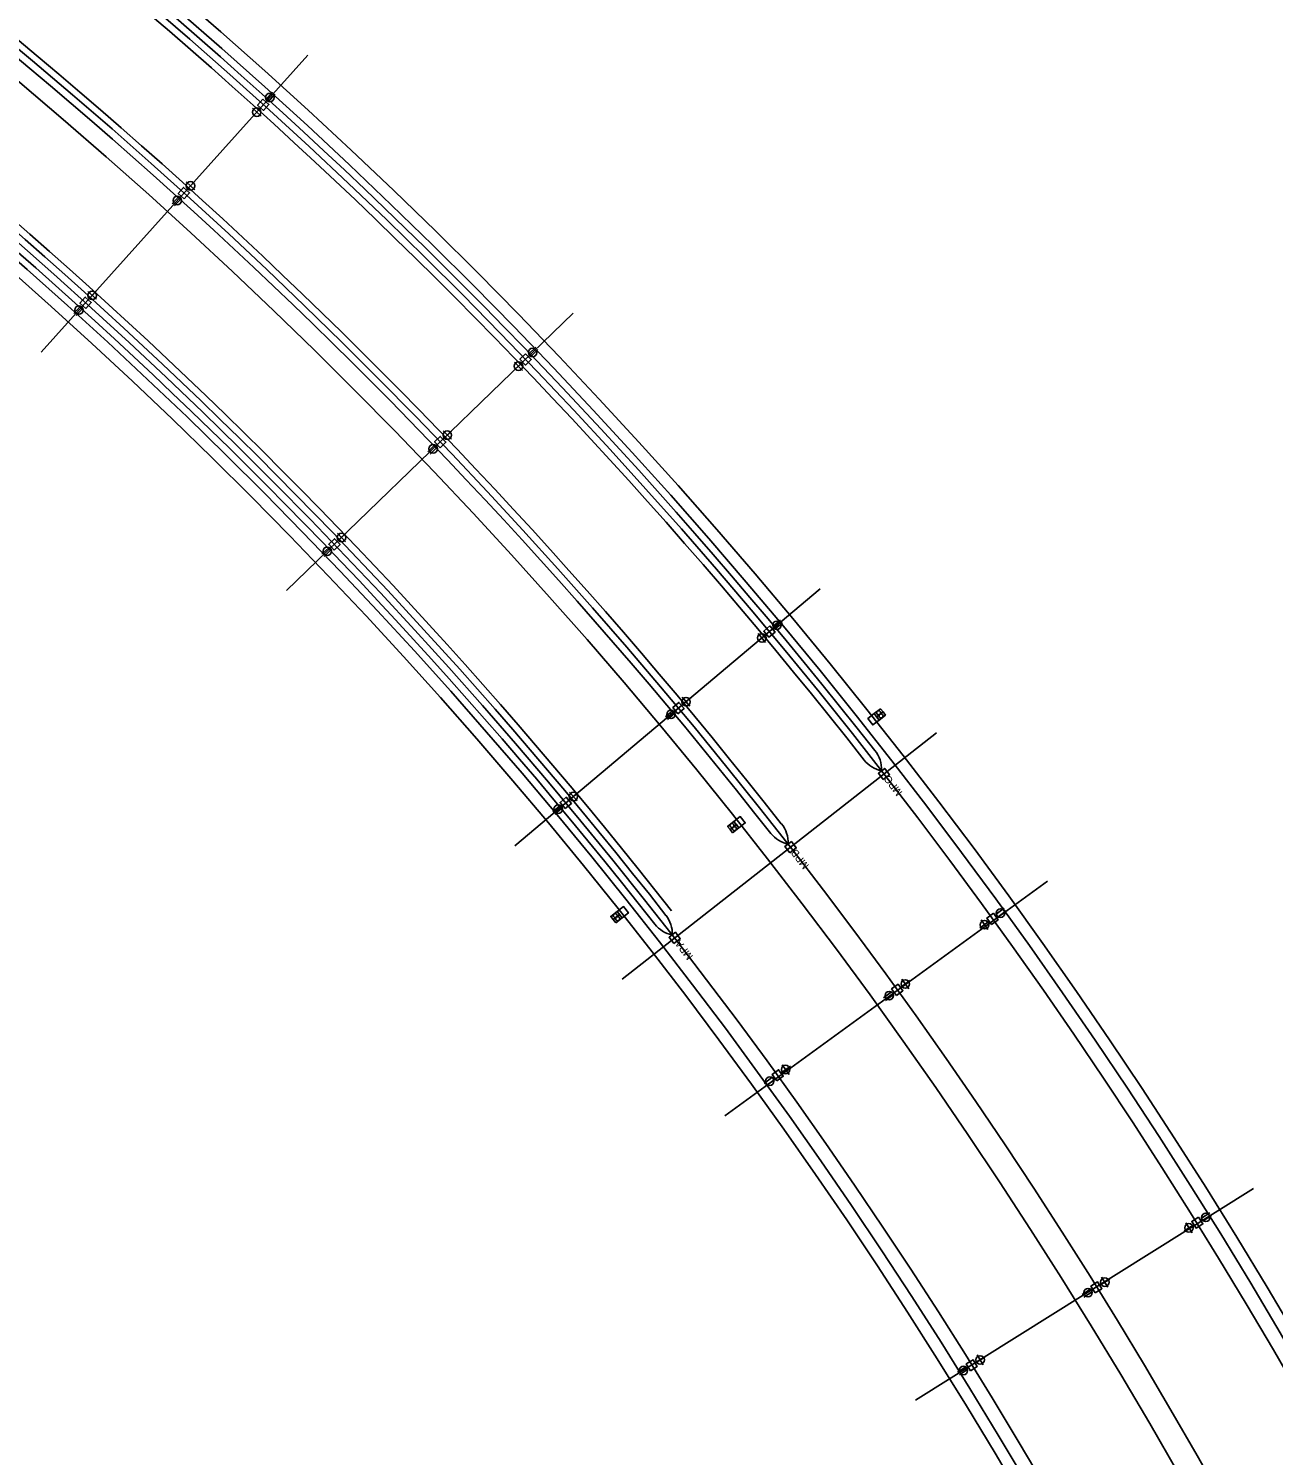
# Model space of a CAD drawing. Extents: x 928165 to 929015, y 635755 to 636543.
# Drawn here: x 928731.1 to 928905.9, y 636137.6 to 636337.8 of the extents above; entities that cross this region are included whole.
import ezdxf

# ---------------------------------------------------------------- set-up
doc = ezdxf.new("R2010")
doc.units = 0
for name, color, linetype in [('AdhocPoint_dp', 7, 'Continuous'), ('ScratchEle_dp', 7, 'Continuous'), ('TextMisc', 7, 'Continuous'), ('TextShtNo', 7, 'Continuous')]:
    doc.layers.add(name, color=color, linetype=linetype)

msp = doc.modelspace()

# ---------------------------------------------------------------- linework, layer by layer
at = {"layer": 'AdhocPoint_dp'}
for points in [[(928764.03, 636327.91), (928764.87, 636327.15), (928764.12, 636326.32), (928763.28, 636327.07)], [(928752.98, 636313.92), (928752.14, 636314.67), (928752.89, 636315.51), (928753.73, 636314.76)], [(928739.17, 636298.55), (928738.33, 636299.3), (928739.08, 636300.14), (928739.92, 636299.38)], [(928800.9, 636292.18), (928801.68, 636291.38), (928800.87, 636290.59), (928800.09, 636291.4)], [(928788.89, 636279), (928788.11, 636279.81), (928788.92, 636280.59), (928789.7, 636279.79)], [(928774.04, 636264.63), (928773.26, 636265.44), (928774.07, 636266.22), (928774.85, 636265.41)], [(928835.18, 636253.98), (928835.9, 636253.12), (928835.04, 636252.39), (928834.32, 636253.25)], [(928822.28, 636241.67), (928821.56, 636242.53), (928822.42, 636243.25), (928823.14, 636242.39)], [(928850.71, 636242.36), (928851.06, 636241.92), (928850.16, 636241.23), (928849.82, 636241.68)], [(928849.82, 636241.68), (928850.51, 636240.78), (928849.62, 636240.1), (928848.93, 636240.99)], [(928851.06, 636241.92), (928851.4, 636241.47), (928850.51, 636240.78), (928850.16, 636241.23)], [(928851.1, 636232.42), (928850.41, 636233.32), (928851.31, 636234), (928851.99, 636233.11)], [(928806.46, 636228.37), (928805.74, 636229.23), (928806.6, 636229.95), (928807.33, 636229.09)], [(928829.59, 636225.41), (928829.25, 636225.86), (928830.14, 636226.54), (928830.48, 636226.1)], [(928830.83, 636225.65), (928830.14, 636226.54), (928831.03, 636227.23), (928831.72, 636226.34)], [(928829.93, 636224.97), (928829.59, 636225.41), (928830.48, 636226.1), (928830.83, 636225.65)], [(928837.98, 636222.15), (928837.29, 636223.04), (928838.19, 636223.73), (928838.87, 636222.83)], [(928814.43, 636213.02), (928813.75, 636213.91), (928814.64, 636214.6), (928815.32, 636213.71)], [(928813.2, 636212.78), (928812.85, 636213.22), (928813.75, 636213.91), (928814.09, 636213.46)], [(928813.54, 636212.33), (928813.2, 636212.78), (928814.09, 636213.46), (928814.43, 636213.02)], [(928866.55, 636213.66), (928867.21, 636212.75), (928866.3, 636212.09), (928865.64, 636213)], [(928821.71, 636209.41), (928821.02, 636210.3), (928821.92, 636210.99), (928822.6, 636210.09)], [(928852.94, 636202.14), (928852.27, 636203.05), (928853.18, 636203.71), (928853.85, 636202.8)], [(928836.15, 636190.13), (928835.49, 636191.03), (928836.4, 636191.7), (928837.06, 636190.79)], [(928895.35, 636171.03), (928895.95, 636170.08), (928895, 636169.48), (928894.4, 636170.43)], [(928880.82, 636160.39), (928880.23, 636161.34), (928881.18, 636161.94), (928881.78, 636160.98)], [(928863.34, 636149.47), (928862.74, 636150.43), (928863.69, 636151.02), (928864.29, 636150.07)]]:
    msp.add_lwpolyline(points, close=True, dxfattribs=at)
for centre in [(928850.44, 636241.8), (928850.78, 636241.35), (928829.86, 636225.98), (928830.21, 636225.53), (928813.47, 636213.34), (928813.82, 636212.9)]:
    msp.add_circle(centre, 0.281, dxfattribs=at)
at = {"layer": 'ScratchEle_dp'}
for centre, radius, start, end in [((928272.36, 635783.24), 736.87, 358.73269, 82.16413), ((928270.99, 635782.23), 735.87, 38.12207, 77.2713), ((928270.99, 635782.23), 733.87, 38.11098, 77.27781), ((928270.99, 635782.23), 734.87, 359.8573, 75.81316), ((928269.66, 635781.44), 716.2, 358.82492, 82.06007), ((928270.99, 635782.23), 719.2, 38.12193, 77.28356), ((928270.99, 635782.23), 717.2, 38.11087, 77.26942), ((928270.99, 635782.23), 718.2, 359.85255, 75.80738), ((928269.58, 635781.3), 695.53, 358.77784, 82.06007), ((928270.99, 635782.23), 698.53, 38.11225, 77.26303), ((928270.99, 635782.23), 696.53, 38.11231, 77.24555), ((928270.99, 635782.23), 697.53, 359.84634, 75.79974), ((928846.76, 636233.87), 4.1, 357.3573, 40.1148), ((928851.64, 636237.69), 4.1, 218.1106, 258.8823), ((928833.65, 636223.58), 4.1, 357.3573, 40.0661), ((928838.53, 636227.41), 4.1, 218.1106, 258.8823), ((928817.38, 636210.83), 4.1, 357.3573, 38.1123), ((928822.25, 636214.66), 4.1, 218.1123, 258.8823)]:
    msp.add_arc(centre, radius, start, end, dxfattribs=at)
at = {"layer": 'TextMisc'}
for p, q in [((928732.89, 636292.4), (928770.32, 636334.06)), ((928767.35, 636258.94), (928807.59, 636297.88)), ((928799.4, 636223.15), (928842.26, 636259.2)), ((928814.46, 636204.44), (928858.55, 636238.97)), ((928828.87, 636185.22), (928874.14, 636218.19)), ((928855.62, 636145.32), (928903.08, 636175.05))]:
    msp.add_line(p, q, dxfattribs=at)
for radius, start, end in [(736.87, 0.06217, 82.06007), (695.53, 0.06217, 82.06007), (699.53, 38.11225, 77.26303)]:
    msp.add_arc((928270.99, 635782.23), radius, start, end, dxfattribs=at)
at = {"layer": 'TextShtNo'}
for p, q in [((928765.38, 636328.9), (928764.46, 636327.88)), ((928765.72, 636328.6), (928764.8, 636327.58)), ((928762.54, 636326.63), (928763.76, 636325.53)), ((928763.7, 636326.69), (928762.6, 636325.47)), ((928764.45, 636327.53), (928764.6, 636327.7)), ((928754.47, 636315.19), (928753.25, 636316.29)), ((928753.31, 636315.13), (928754.41, 636316.36)), ((928752.56, 636314.3), (928752.41, 636314.13)), ((928751.3, 636313.22), (928752.21, 636314.25)), ((928751.63, 636312.92), (928752.55, 636313.95)), ((928740.66, 636299.82), (928739.44, 636300.92)), ((928739.5, 636299.76), (928740.6, 636300.98)), ((928737.48, 636297.85), (928738.4, 636298.87)), ((928737.82, 636297.55), (928738.74, 636298.57)), ((928738.75, 636298.92), (928738.6, 636298.76)), ((928802.31, 636293.09), (928801.32, 636292.13)), ((928802.63, 636292.76), (928801.64, 636291.81)), ((928800.48, 636291), (928799.3, 636289.86)), ((928799.32, 636291.02), (928800.46, 636289.84)), ((928801.29, 636291.78), (928801.45, 636291.94)), ((928789.31, 636280.19), (928790.49, 636281.33)), ((928790.47, 636280.17), (928789.33, 636281.35)), ((928787.17, 636278.43), (928788.15, 636279.38)), ((928787.48, 636278.1), (928788.47, 636279.06)), ((928788.5, 636279.41), (928788.34, 636279.25)), ((928774.46, 636265.82), (928775.64, 636266.96)), ((928775.62, 636265.8), (928774.48, 636266.98)), ((928772.31, 636264.05), (928773.3, 636265.01)), ((928772.63, 636263.73), (928773.62, 636264.69)), ((928773.65, 636265.04), (928773.49, 636264.88)), ((928836.65, 636254.78), (928835.6, 636253.89)), ((928836.94, 636254.43), (928835.89, 636253.55)), ((928834.68, 636252.82), (928833.42, 636251.77)), ((928833.52, 636252.92), (928834.58, 636251.67)), ((928835.54, 636253.55), (928835.71, 636253.69)), ((928822.78, 636242.82), (928824.04, 636243.88)), ((928823.94, 636242.72), (928822.88, 636243.98)), ((928820.52, 636241.22), (928821.57, 636242.1)), ((928820.81, 636240.87), (928821.86, 636241.75)), ((928821.92, 636242.1), (928821.75, 636241.95)), ((928806.97, 636229.52), (928808.23, 636230.57)), ((928808.12, 636229.42), (928807.07, 636230.68)), ((928804.7, 636227.92), (928805.75, 636228.8)), ((928804.99, 636227.57), (928806.04, 636228.45)), ((928806.1, 636228.8), (928805.93, 636228.65)), ((928868.07, 636214.36), (928866.96, 636213.55)), ((928865.97, 636212.55), (928864.64, 636211.58)), ((928864.82, 636212.73), (928865.79, 636211.4)), ((928866.88, 636213.21), (928867.06, 636213.34)), ((928868.34, 636213.99), (928867.23, 636213.18)), ((928853.51, 636203.26), (928854.84, 636204.22)), ((928854.66, 636203.07), (928853.7, 636204.4)), ((928851.14, 636201.81), (928852.26, 636202.62)), ((928851.41, 636201.44), (928852.52, 636202.25)), ((928852.61, 636202.59), (928852.42, 636202.46)), ((928836.73, 636191.24), (928838.06, 636192.21)), ((928837.88, 636191.06), (928836.91, 636192.39)), ((928834.36, 636189.79), (928835.47, 636190.6)), ((928834.63, 636189.43), (928835.74, 636190.24)), ((928835.82, 636190.58), (928835.64, 636190.45)), ((928893.57, 636170.22), (928894.44, 636168.82)), ((928895.65, 636170.55), (928895.84, 636170.67)), ((928896.92, 636171.62), (928895.76, 636170.89)), ((928897.16, 636171.23), (928896, 636170.5)), ((928894.7, 636169.96), (928893.31, 636169.08)), ((928881.48, 636161.46), (928882.87, 636162.33)), ((928882.61, 636161.2), (928881.74, 636162.59)), ((928879.01, 636160.18), (928880.18, 636160.91)), ((928879.25, 636159.8), (928880.42, 636160.53)), ((928880.53, 636160.86), (928880.33, 636160.75)), ((928863.99, 636150.55), (928865.39, 636151.42)), ((928865.13, 636150.29), (928864.25, 636151.68)), ((928861.53, 636149.27), (928862.69, 636150)), ((928861.77, 636148.89), (928862.93, 636149.62)), ((928863.04, 636149.95), (928862.85, 636149.83))]:
    msp.add_line(p, q, dxfattribs=at)
for centre in [(928765, 636328.14), (928763.15, 636326.08), (928753.86, 636315.74), (928752.01, 636313.68), (928740.05, 636300.37), (928738.2, 636298.31), (928801.88, 636292.35), (928799.89, 636290.43), (928789.9, 636280.76), (928787.91, 636278.84), (928775.05, 636266.39), (928773.06, 636264.46), (928836.17, 636254.08), (928834.05, 636252.3), (928823.41, 636243.35), (928821.29, 636241.57), (928807.6, 636230.05), (928805.47, 636228.27), (928867.54, 636213.69), (928865.3, 636212.06), (928854.18, 636203.74), (928851.94, 636202.11), (928837.39, 636191.73), (928835.16, 636190.1), (928894, 636169.52), (928896.35, 636170.99), (928882.18, 636161.9), (928879.83, 636160.43), (928862.34, 636149.51), (928864.69, 636150.98)]:
    msp.add_circle(centre, 0.597, dxfattribs=at)

# ---------------------------------------------------------------- texts
for s, p in [('MPC', (928853.85, 636230.64)), ('MPB', (928840.73, 636220.37)), ('MPA', (928824.46, 636207.63))]:
    msp.add_text(s, height=1.05, rotation=127.6603, dxfattribs=at).set_placement(p)

doc.saveas('drawing.dxf')
